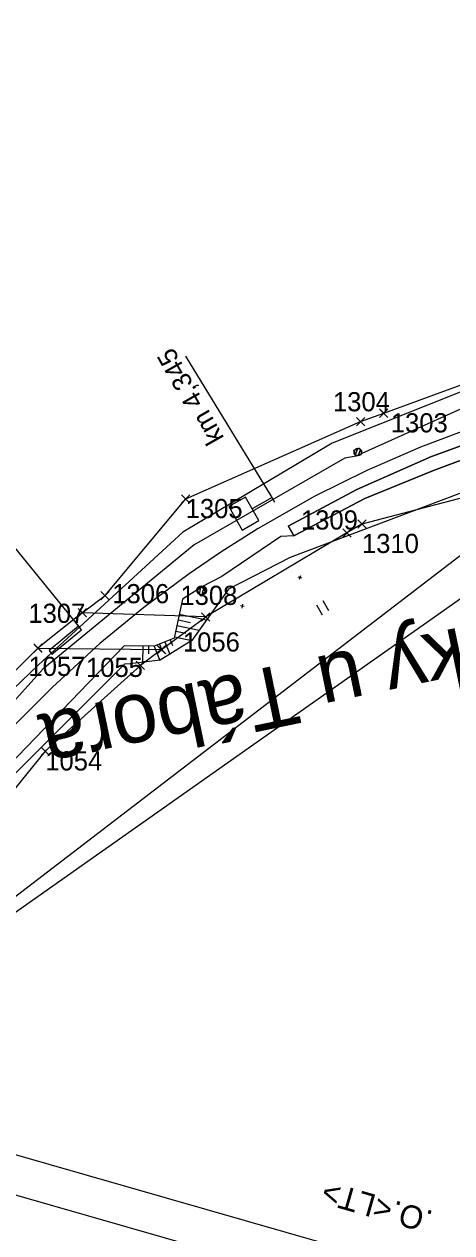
# Model space of a CAD drawing. Extents: x -738085 to -734426, y -1122197 to -1119748.
# Drawn here: x -737468.6 to -737412.8, y -1121531.4 to -1121373.8 of the extents above; entities that cross this region are included whole.
import ezdxf

# ---------------------------------------------------------------- set-up
doc = ezdxf.new("R2010")
doc.units = 0
for name, color, linetype in [('SŽDC', 7, 'Continuous'), ('Trvalý zábor', 7, 'Continuous'), ('Vrstva 1', 7, 'Continuous'), ('Vrstva 11', 7, 'Continuous'), ('Vrstva 12', 7, 'Continuous'), ('Vrstva 14', 7, 'Continuous'), ('Vrstva 23', 7, 'Continuous'), ('Vrstva 48', 7, 'Continuous'), ('Vrstva 49', 7, 'Continuous'), ('Vrstva 58', 7, 'Continuous'), ('Vrstva 60', 7, 'Continuous'), ('Vrstva 63', 7, 'Continuous'), ('Vrstva 7', 7, 'Continuous'), ('Vrstva 9', 7, 'Continuous')]:
    doc.layers.add(name, color=color, linetype=linetype)

msp = doc.modelspace()

# ---------------------------------------------------------------- linework, layer by layer
at = {"layer": 'SŽDC'}
for p, q in [((-737426.47, -1121440.12), (-737444.92, -1121451.07)), ((-737461.03, -1121450.52), (-737458.06, -1121448.28)), ((-737444.92, -1121451.07), (-737461.03, -1121450.52)), ((-737466.82, -1121455.14), (-737450.69, -1121455.32))]:
    msp.add_line(p, q, dxfattribs=at)
for points in [[(-737421.67, -1121424.5), (-737411.54, -1121420.81), (-737402.12, -1121416.14), (-737373.02, -1121411.21), (-737354.93, -1121411.64)], [(-737458.06, -1121448.28), (-737447.53, -1121435.68), (-737424.69, -1121425.6), (-737421.67, -1121424.5)], [(-737402.13, -1121433.1), (-737424.51, -1121438.96), (-737426.47, -1121440.12)], [(-737510.61, -1121532.89), (-737503.77, -1121510.31), (-737493.54, -1121488.02), (-737480.94, -1121469.09), (-737466.82, -1121455.14)], [(-737450.69, -1121455.32), (-737453.45, -1121457.39), (-737465.87, -1121468.59)], [(-737465.87, -1121468.59), (-737481.22, -1121487.43), (-737485.71, -1121494.9), (-737493.58, -1121508.22), (-737499.12, -1121522.51), (-737503.53, -1121537.17)]]:
    msp.add_lwpolyline(points, dxfattribs=at)
at = {"layer": 'Trvalý zábor'}
for p, q in [((-737461.03, -1121450.52), (-737466.82, -1121455.14)), ((-737444.92, -1121451.07), (-737461.03, -1121450.52)), ((-737450.69, -1121455.32), (-737444.92, -1121451.07)), ((-737466.82, -1121455.14), (-737450.69, -1121455.32))]:
    msp.add_line(p, q, dxfattribs=at)
at = {"layer": 'Vrstva 1'}
for points in [[(-736726.43, -1121430.48), (-737533.93, -1121199.12), (-737615.73, -1121484.62), (-736808.23, -1121715.98)], [(-737530.5, -1121205.3), (-736732.61, -1121433.9), (-736811.65, -1121709.79), (-737609.54, -1121481.19)]]:
    msp.add_lwpolyline(points, close=True, dxfattribs=at)
msp.add_lwpolyline([(-737302.82, -1121423.99), (-737322.07, -1121421.44), (-737328.44, -1121420.59), (-737334.37, -1121419.85), (-737341.18, -1121419.08), (-737346.17, -1121418.63), (-737355.36, -1121418.09), (-737364.19, -1121418.05), (-737371.06, -1121418.37), (-737378.94, -1121419.13), (-737386.42, -1121420.24), (-737394.37, -1121421.82), (-737402.27, -1121423.87), (-737409.27, -1121426.07), (-737416.85, -1121428.91), (-737423.86, -1121431.97), (-737430.65, -1121435.33), (-737438.05, -1121439.53), (-737442.95, -1121442.62), (-737447.09, -1121445.44), (-737453.01, -1121449.85), (-737458.73, -1121454.55), (-737464.94, -1121460.22), (-737469.92, -1121465.24)], dxfattribs=at)
msp.add_lwpolyline([(-737302.82, -1121423.99), (-737322.07, -1121421.44), (-737328.44, -1121420.59), (-737334.37, -1121419.85), (-737341.18, -1121419.08), (-737346.17, -1121418.63), (-737355.36, -1121418.09), (-737364.19, -1121418.05), (-737371.06, -1121418.37), (-737378.94, -1121419.13), (-737386.42, -1121420.24), (-737394.37, -1121421.82), (-737402.27, -1121423.87), (-737409.27, -1121426.07), (-737416.85, -1121428.91), (-737423.86, -1121431.97), (-737430.65, -1121435.33), (-737438.05, -1121439.53), (-737442.95, -1121442.62), (-737447.09, -1121445.44), (-737453.01, -1121449.85), (-737458.73, -1121454.55), (-737464.94, -1121460.22), (-737469.92, -1121465.24)], dxfattribs=at)
at = {"layer": 'Vrstva 11'}
for p, q in [((-737425.05, -1121429.07), (-737425.39, -1121429.93)), ((-737424.7, -1121429.21), (-737425.04, -1121430.06)), ((-737445.58, -1121447.2), (-737445.79, -1121448.11)), ((-737445.22, -1121447.29), (-737445.42, -1121448.18))]:
    msp.add_line(p, q, dxfattribs=at)
for centre in [(-737425.05, -1121429.57), (-737445.51, -1121447.7)]:
    msp.add_circle(centre, 0.5, dxfattribs=at)
at = {"layer": 'Vrstva 12'}
for p, q in [((-737424.84, -1121429.04), (-737425.58, -1121429.36)), ((-737444.95, -1121447.8), (-737445.61, -1121448.25))]:
    msp.add_line(p, q, dxfattribs=at)
for points in [[(-737424.52, -1121429.77), (-737425.26, -1121430.09), (-737425.58, -1121429.36), (-737424.84, -1121429.04), (-737424.52, -1121429.77)], [(-737425.58, -1121429.36), (-737425.58, -1121429.36), (-737425.26, -1121430.09)], [(-737424.84, -1121429.04), (-737424.84, -1121429.04), (-737424.52, -1121429.77)], [(-737446.07, -1121447.59), (-737445.4, -1121447.14), (-737444.95, -1121447.8), (-737445.61, -1121448.25), (-737446.07, -1121447.59)], [(-737445.4, -1121447.14), (-737444.95, -1121447.8), (-737444.95, -1121447.8)], [(-737446.07, -1121447.59), (-737445.61, -1121448.25), (-737445.61, -1121448.25)]]:
    msp.add_lwpolyline(points, dxfattribs=at)
at = {"layer": 'Vrstva 14'}
for points in [[(-737434.16, -1121439.21), (-737425.16, -1121434.45), (-737415.44, -1121430.13), (-737407.49, -1121427.26), (-737399.47, -1121424.82), (-737391.57, -1121422.9), (-737382.54, -1121421.31), (-737373.94, -1121420.28), (-737365.39, -1121419.77), (-737357.2, -1121419.69), (-737355.17, -1121419.79)], [(-737425.16, -1121434.45), (-737434.16, -1121439.21), (-737433.42, -1121440.49), (-737424.14, -1121435.61), (-737415.18, -1121431.98), (-737406.88, -1121428.88), (-737397.66, -1121426.46), (-737389.2, -1121424.1), (-737388.14, -1121424.84), (-737384.26, -1121424.12), (-737383.6, -1121423.16), (-737372.5, -1121421.89), (-737357.71, -1121421.58), (-737355.17, -1121419.79)], [(-737355.17, -1121419.79), (-737357.2, -1121419.69), (-737365.39, -1121419.77), (-737373.94, -1121420.28), (-737382.54, -1121421.31), (-737391.57, -1121422.9), (-737399.47, -1121424.82), (-737407.49, -1121427.26), (-737415.44, -1121430.13), (-737425.16, -1121434.45)]]:
    msp.add_lwpolyline(points, dxfattribs=at)
at = {"layer": 'Vrstva 48'}
for p, q in [((-737448.53, -1121451.46), (-737446.9, -1121451.79)), ((-737448.38, -1121450.72), (-737444.8, -1121451.46)), ((-737448.98, -1121453.66), (-737446.71, -1121454.13)), ((-737448.83, -1121452.92), (-737447.53, -1121453.19)), ((-737448.68, -1121452.19), (-737445.75, -1121452.79)), ((-737453.13, -1121454.88), (-737453.16, -1121456.99)), ((-737452.38, -1121454.88), (-737452.39, -1121455.89)), ((-737451.63, -1121454.89), (-737450.9, -1121456.73)), ((-737450.94, -1121454.61), (-737450.59, -1121455.47)), ((-737450.24, -1121454.33), (-737449.6, -1121455.94)), ((-737449.55, -1121454.05), (-737449.25, -1121454.79))]:
    msp.add_line(p, q, dxfattribs=at)
at = {"layer": 'Vrstva 49'}
for p, q in [((-737432.55, -1121445.7), (-737432.69, -1121446.18)), ((-737432.38, -1121446), (-737432.86, -1121445.87)), ((-737439.9, -1121449.71), (-737440.39, -1121449.62)), ((-737440.1, -1121449.42), (-737440.19, -1121449.91))]:
    msp.add_line(p, q, dxfattribs=at)
for points in [[(-737355.47, -1121412.32), (-737367.21, -1121412.69), (-737377.95, -1121412.78), (-737396.2, -1121415.99), (-737409.71, -1121420.96), (-737428.4, -1121428.4), (-737447.9, -1121440), (-737466.76, -1121457.31), (-737479.09, -1121469.07), (-737494.02, -1121491.43), (-737502.64, -1121510.6), (-737503.11, -1121511.74), (-737503.41, -1121512.48), (-737507.86, -1121528.05), (-737513.25, -1121551.43), (-737518.11, -1121577.51), (-737528.1, -1121607.82), (-737533.62, -1121619.3), (-737538.45, -1121627.34), (-737537.78, -1121628.5)], [(-737354.91, -1121414.28), (-737363.93, -1121414.85), (-737364.76, -1121414.89), (-737367.31, -1121414.88), (-737377.52, -1121416.55), (-737394.83, -1121419.38), (-737409.03, -1121422.78), (-737424.52, -1121429.77), (-737425.26, -1121430.09), (-737426.75, -1121430.35), (-737446.44, -1121441.67), (-737466.18, -1121457.87), (-737471.18, -1121463.45), (-737471.74, -1121464.01), (-737477.78, -1121470.26), (-737492.77, -1121492.11), (-737501.93, -1121510.89), (-737502.37, -1121512.04), (-737502.67, -1121512.78), (-737507.86, -1121528.05)], [(-737387.69, -1121427.45), (-737388.14, -1121424.84), (-737392.19, -1121425.63), (-737397.66, -1121426.46), (-737406.88, -1121428.88), (-737415.18, -1121431.98), (-737424.14, -1121435.61), (-737433.42, -1121440.49), (-737435.11, -1121440.57)], [(-737387.69, -1121427.45), (-737411.86, -1121435), (-737433.88, -1121443.3)], [(-737435.11, -1121440.57), (-737442.83, -1121445.78), (-737445.4, -1121447.14), (-737446.07, -1121447.59), (-737447.96, -1121448.73), (-737449.02, -1121453.84), (-737451.65, -1121454.89), (-737455.57, -1121454.85), (-737474.15, -1121474.03), (-737487.17, -1121494.48)], [(-737433.88, -1121443.3), (-737441.92, -1121447.46), (-737446.73, -1121454.15), (-737450.86, -1121456.72), (-737454.77, -1121457.18), (-737455.53, -1121457.22), (-737473.31, -1121474.96), (-737487.17, -1121494.48), (-737497.62, -1121515.22), (-737502.7, -1121530.64), (-737504.71, -1121541.22), (-737504.9, -1121542.2), (-737508.13, -1121557.44), (-737514.88, -1121589.78), (-737521.54, -1121608.87), (-737522.08, -1121610.28), (-737522.51, -1121611.18), (-737527.69, -1121621.79), (-737532.98, -1121629.72), (-737534.58, -1121630.34)]]:
    msp.add_lwpolyline(points, dxfattribs=at)
at = {"layer": 'Vrstva 58'}
for p, q in [((-737430.44, -1121449.47), (-737429.71, -1121450.78)), ((-737428.83, -1121450.29), (-737429.57, -1121448.98))]:
    msp.add_line(p, q, dxfattribs=at)
at = {"layer": 'Vrstva 60'}
for p, q in [((-737424.24, -1121426.05), (-737425.24, -1121425.05)), ((-737424.24, -1121425.15), (-737425.24, -1121426.15)), ((-737425.14, -1121426.05), (-737424.14, -1121425.05)), ((-737425.14, -1121425.15), (-737424.14, -1121426.15)), ((-737421.22, -1121424.95), (-737422.22, -1121423.95)), ((-737421.22, -1121424.05), (-737422.22, -1121425.05)), ((-737422.12, -1121424.95), (-737421.12, -1121423.95)), ((-737422.12, -1121424.05), (-737421.12, -1121425.05)), ((-737421.67, -1121424.5), (-737421.67, -1121424.5)), ((-737424.69, -1121425.6), (-737424.69, -1121425.6)), ((-737447.08, -1121436.13), (-737448.08, -1121435.13)), ((-737447.08, -1121435.23), (-737448.08, -1121436.23)), ((-737447.98, -1121436.13), (-737446.98, -1121435.13)), ((-737447.98, -1121435.23), (-737446.98, -1121436.23)), ((-737447.53, -1121435.68), (-737447.53, -1121435.68)), ((-737424.06, -1121439.41), (-737425.06, -1121438.41)), ((-737424.06, -1121438.51), (-737425.06, -1121439.51)), ((-737424.96, -1121439.41), (-737423.96, -1121438.41)), ((-737424.96, -1121438.51), (-737423.96, -1121439.51)), ((-737424.51, -1121438.96), (-737424.51, -1121438.96)), ((-737426.02, -1121440.57), (-737427.02, -1121439.57)), ((-737426.02, -1121439.67), (-737427.02, -1121440.67)), ((-737426.92, -1121440.57), (-737425.92, -1121439.57)), ((-737426.92, -1121439.67), (-737425.92, -1121440.67)), ((-737426.47, -1121440.12), (-737426.47, -1121440.12)), ((-737457.61, -1121448.73), (-737458.61, -1121447.73)), ((-737457.61, -1121447.83), (-737458.61, -1121448.83)), ((-737458.51, -1121448.73), (-737457.51, -1121447.73)), ((-737458.51, -1121447.83), (-737457.51, -1121448.83)), ((-737458.06, -1121448.28), (-737458.06, -1121448.28)), ((-737460.58, -1121450.97), (-737461.58, -1121449.97)), ((-737460.58, -1121450.07), (-737461.58, -1121451.07)), ((-737461.48, -1121450.97), (-737460.48, -1121449.97)), ((-737461.48, -1121450.07), (-737460.48, -1121451.07)), ((-737461.03, -1121450.52), (-737461.03, -1121450.52)), ((-737444.47, -1121451.52), (-737445.47, -1121450.52)), ((-737445.37, -1121451.52), (-737444.37, -1121450.52)), ((-737444.47, -1121450.62), (-737445.47, -1121451.62)), ((-737445.37, -1121450.62), (-737444.37, -1121451.62)), ((-737444.92, -1121451.07), (-737444.92, -1121451.07)), ((-737466.37, -1121455.59), (-737467.37, -1121454.59)), ((-737466.37, -1121454.69), (-737467.37, -1121455.69)), ((-737467.27, -1121455.59), (-737466.27, -1121454.59)), ((-737467.27, -1121454.69), (-737466.27, -1121455.69)), ((-737466.82, -1121455.14), (-737466.82, -1121455.14)), ((-737450.24, -1121455.77), (-737451.24, -1121454.77)), ((-737450.24, -1121454.87), (-737451.24, -1121455.87)), ((-737451.14, -1121455.77), (-737450.14, -1121454.77)), ((-737451.14, -1121454.87), (-737450.14, -1121455.87)), ((-737450.69, -1121455.32), (-737450.69, -1121455.32)), ((-737453, -1121457.84), (-737454, -1121456.84)), ((-737453, -1121456.94), (-737454, -1121457.94)), ((-737453.9, -1121457.84), (-737452.9, -1121456.84)), ((-737453.9, -1121456.94), (-737452.9, -1121457.94)), ((-737453.45, -1121457.39), (-737453.45, -1121457.39)), ((-737465.42, -1121469.04), (-737466.42, -1121468.04)), ((-737465.42, -1121468.14), (-737466.42, -1121469.14)), ((-737466.32, -1121469.04), (-737465.32, -1121468.04)), ((-737466.32, -1121468.14), (-737465.32, -1121469.14)), ((-737465.87, -1121468.59), (-737465.87, -1121468.59))]:
    msp.add_line(p, q, dxfattribs=at)
at = {"layer": 'Vrstva 63'}
for p, q in [((-737502.71, -1121512.73), (-737376.13, -1121415.82)), ((-737502.61, -1121512.64), (-737364.62, -1121415.63))]:
    msp.add_line(p, q, dxfattribs=at)
at = {"layer": 'Vrstva 7'}
for p, q in [((-737436.24, -1121435.49), (-737447.53, -1121417.06)), ((-737435.87, -1121436.15), (-737436.61, -1121434.84))]:
    msp.add_line(p, q, dxfattribs=at)
msp.add_lwpolyline([(-737436.24, -1121435.49), (-737438.85, -1121436.97), (-737439.72, -1121435.45), (-737441.89, -1121436.68), (-737440.17, -1121439.73), (-737437.99, -1121438.49), (-737438.85, -1121436.97)], dxfattribs=at)
at = {"layer": 'Vrstva 9'}
for p, q in [((-737461.32, -1121452.5), (-737475.52, -1121435.08)), ((-737461.51, -1121452.27), (-737461.89, -1121451.8)), ((-737461.51, -1121452.27), (-737465.37, -1121455.44)), ((-737464.99, -1121455.9), (-737461.12, -1121452.73)), ((-737461.12, -1121452.73), (-737461.51, -1121452.27)), ((-737465.37, -1121455.44), (-737464.99, -1121455.9))]:
    msp.add_line(p, q, dxfattribs=at)

# ---------------------------------------------------------------- texts
at = {"layer": 'Vrstva 1'}
msp.add_text('.O.<LT>', height=3, rotation=164.0124, dxfattribs=at).set_placement((-737415.08, -1121528.6))
at = {"layer": 'Vrstva 23'}
msp.add_text('zast. Horky u Tábora', height=8, rotation=191.7302, dxfattribs=at).set_placement((-737369.8, -1121443.69))
at = {"layer": 'Vrstva 60'}
for s, p in [('1304', (-737428.3, -1121424.25)), ('1303', (-737420.74, -1121427)), ('1305', (-737447.53, -1121438.18)), ('1309', (-737432.48, -1121439.67)), ('1310', (-737424.51, -1121442.73)), ('1306', (-737457.12, -1121449.28)), ('1308', (-737448.22, -1121449.5)), ('1307', (-737468.07, -1121451.84)), ('1056', (-737447.89, -1121455.58)), ('1057', (-737468.06, -1121458.76)), ('1055', (-737460.55, -1121458.89)), ('1054', (-737465.87, -1121471.09))]:
    msp.add_text(s, height=2.5, dxfattribs=at).set_placement(p)
at = {"layer": 'Vrstva 7'}
msp.add_text('km 4,345', height=2.5, rotation=119.5368, dxfattribs=at).set_placement((-737442.45, -1121427.73))

doc.saveas('drawing.dxf')
